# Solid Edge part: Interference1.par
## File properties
Last saved by: user
Revision: 51
Accuracy: 0.99
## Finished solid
Body 1: solid body, 4 faces, 4 edges, 2 vertices.
  Faces by surface: cone 2, plane 2
  Edges by curve: circle 2, intersection 1, line 1
Bounding box of the edges (mm): 0.037 x 0.085 x 0.148, from (0.5503, -0.0852, 10.9259) to (0.587, 0, 11.0741).
Conical faces (half-angle, radius in mm at the cone's reference point): 27.3968 deg R0.0554 x2
Planar faces by outward normal: +x 1, oblique 1
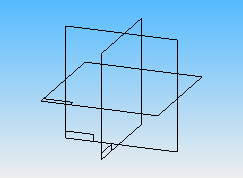
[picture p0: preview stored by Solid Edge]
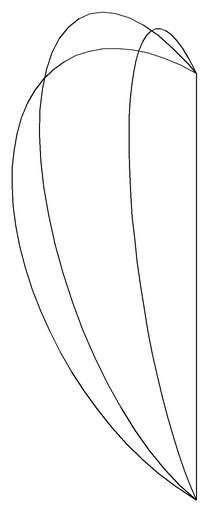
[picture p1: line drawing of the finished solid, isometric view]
